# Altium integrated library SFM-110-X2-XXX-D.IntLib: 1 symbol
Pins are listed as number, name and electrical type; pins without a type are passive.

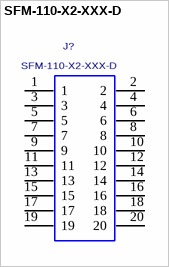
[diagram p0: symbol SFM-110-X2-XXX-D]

## SFM-110-X2-XXX-D
designator J?
SOCKET STRIP, .050" (1.27mm) PITCH, SURFACE MOUNT.; MANUFACTURER: SAMTEC
footprint SFM-110-X2-XXX-D
pins: 1, 2, 3, 4, 5, 6, 7, 8, 9, 10, 11, 12, 13, 14, 15, 16, 17, 18, 19, 20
